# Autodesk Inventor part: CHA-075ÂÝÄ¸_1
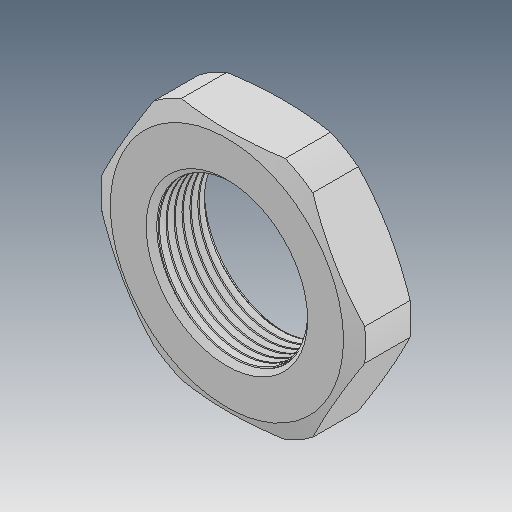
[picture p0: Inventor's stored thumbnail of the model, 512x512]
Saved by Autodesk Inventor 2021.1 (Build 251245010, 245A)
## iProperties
Created: 2019-12
Part Number: CHA-075ÂÝÄ¸_1
Material: Ogólny
Document SubType Name: Modeling
Designer: user
Density: 1 g/cm^3
Appearance: Domyślna
Author: user
Revision Number: ÈÎºÎ
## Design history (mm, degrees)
feature "ÊäÈë1"
node "Bryła1"
